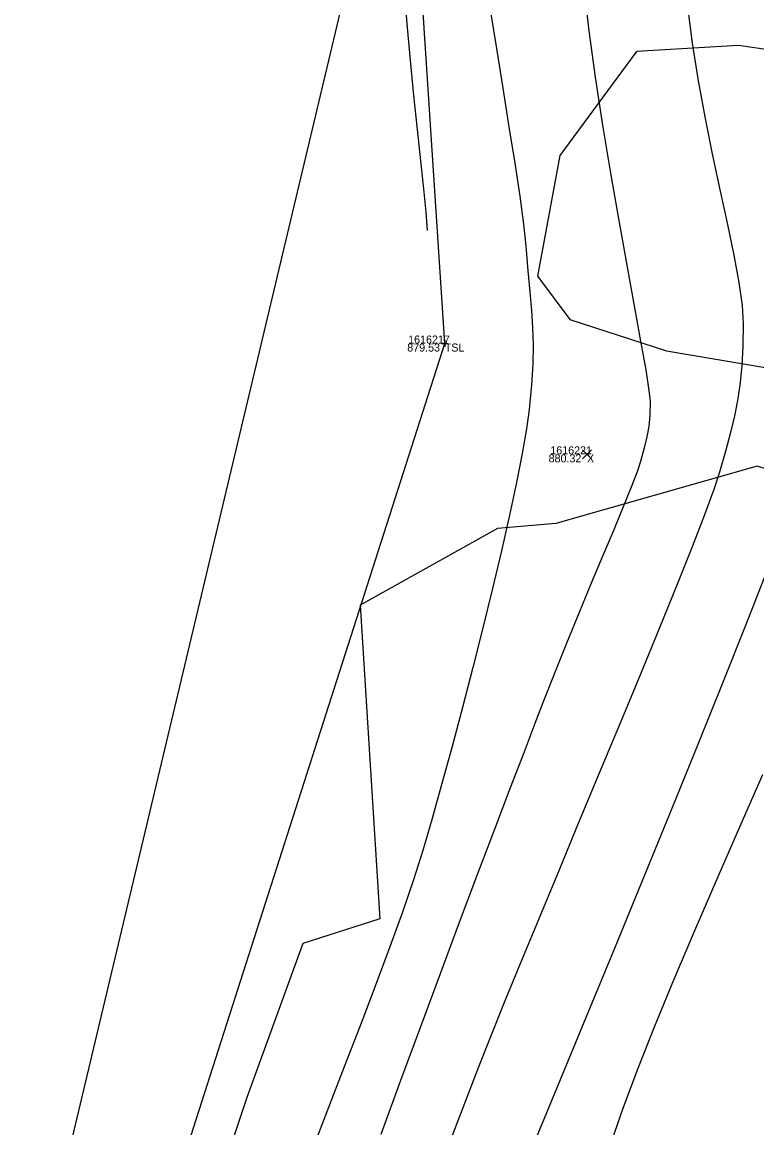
# Model space of a CAD drawing. Extents: x 1957117 to 1971063, y 701601 to 715861.
# Drawn here: x 1963273.02 to 1963305.15, y 706062.39 to 706110.73 of the extents above; entities that cross this region are included whole.
import ezdxf

# ---------------------------------------------------------------- set-up
doc = ezdxf.new("R2010")
doc.units = 0
for name, color, linetype in [('AP_X_Lights', 7, 'Continuous'), ('DT_X_Break_Line', 7, 'Continuous'), ('DT_X_Contour_Major', 7, 'Continuous'), ('DT_X_Contour_Minor', 7, 'Continuous'), ('DT_X_TIN_Hull', 7, 'Continuous'), ('HY_X_Water_Edge', 7, 'Continuous'), ('PV_P_Drive', 7, 'Continuous'), ('PV_P_Shoulder', 7, 'Continuous'), ('RS_Raster1', 7, 'Continuous'), ('SC_Scratch1', 7, 'Continuous'), ('SC_Shading5', 7, 'Continuous'), ('VG_X_Tree_Line_Rt', 7, 'Continuous')]:
    doc.layers.add(name, color=color, linetype=linetype)

msp = doc.modelspace()

# ---------------------------------------------------------------- linework, layer by layer
at = {"layer": 'AP_X_Lights'}
for p, q in [((1963297.524, 706091.639), (1963297.912, 706092.029)), ((1963297.524, 706092.029), (1963297.912, 706091.639))]:
    msp.add_line(p, q, dxfattribs=at)
at = {"layer": 'DT_X_Break_Line'}
msp.add_lwpolyline([(1963218.329, 705756.178), (1963229.265, 705808.356), (1963234.8, 705853.147), (1963240.079, 705903.468), (1963258.033, 705954.684), (1963270.287, 705999.321), (1963276.323, 706049.345), (1963291.502, 706096.678), (1963290.138, 706117.655), (1963319.921, 706191.295), (1963330.374, 706242.631), (1963344.413, 706289.409), (1963345.772, 706340.009), (1963383.117, 706434.704), (1963392.11, 706487.426), (1963408.164, 706535.687), (1963423.633, 706582.721), (1963435.242, 706630.63), (1963443.084, 706680.696), (1963464.732, 706726.815), (1963480.654, 706774.214), (1963508.465, 706799.669), (1963511.002, 706809.48)], dxfattribs=at)
at = {"layer": 'DT_X_Contour_Major'}
for points in [[(1963289.725, 706112.211), (1963289.847, 706110.647), (1963289.988, 706109.069), (1963290.14, 706107.519), (1963290.293, 706106.037), (1963290.439, 706104.666), (1963290.568, 706103.446), (1963290.671, 706102.418), (1963290.738, 706101.624)], [(1963289.725, 706112.211), (1963289.847, 706110.647), (1963289.988, 706109.069), (1963290.14, 706107.519), (1963290.293, 706106.037), (1963290.439, 706104.666), (1963290.568, 706103.446), (1963290.671, 706102.418), (1963290.738, 706101.624)], [(1963293.493, 706111.269), (1963293.759, 706109.572), (1963294.037, 706107.847), (1963294.309, 706106.155), (1963294.562, 706104.558), (1963294.779, 706103.116), (1963294.945, 706101.891), (1963295.044, 706100.942), (1963295.135, 706099.857), (1963295.219, 706098.933), (1963295.29, 706098.118), (1963295.34, 706097.358), (1963295.363, 706096.6), (1963295.352, 706095.789), (1963295.299, 706094.873), (1963295.199, 706093.797), (1963295.081, 706092.951), (1963294.892, 706091.876), (1963294.639, 706090.608), (1963294.332, 706089.178), (1963293.978, 706087.62), (1963293.587, 706085.967), (1963293.167, 706084.252), (1963292.728, 706082.509), (1963292.277, 706080.77), (1963291.824, 706079.069), (1963291.377, 706077.438), (1963290.946, 706075.911), (1963290.537, 706074.521), (1963290.13, 706073.235), (1963289.647, 706071.825), (1963289.101, 706070.31), (1963288.505, 706068.708), (1963287.87, 706067.04), (1963287.21, 706065.325), (1963286.536, 706063.582), (1963285.862, 706061.831)], [(1963293.493, 706111.269), (1963293.759, 706109.572), (1963294.037, 706107.847), (1963294.309, 706106.155), (1963294.562, 706104.558), (1963294.779, 706103.116), (1963294.945, 706101.891), (1963295.044, 706100.942), (1963295.135, 706099.857), (1963295.219, 706098.933), (1963295.29, 706098.118), (1963295.34, 706097.358), (1963295.363, 706096.6), (1963295.352, 706095.789), (1963295.299, 706094.873), (1963295.199, 706093.797), (1963295.081, 706092.951), (1963294.892, 706091.876), (1963294.639, 706090.608), (1963294.332, 706089.178), (1963293.978, 706087.62), (1963293.587, 706085.967), (1963293.167, 706084.252), (1963292.728, 706082.509), (1963292.277, 706080.77), (1963291.824, 706079.069), (1963291.377, 706077.438), (1963290.946, 706075.911), (1963290.537, 706074.521), (1963290.13, 706073.235), (1963289.647, 706071.825), (1963289.101, 706070.31), (1963288.505, 706068.708), (1963287.87, 706067.04), (1963287.21, 706065.325), (1963286.536, 706063.582), (1963285.862, 706061.831)]]:
    msp.add_lwpolyline(points, dxfattribs=at)
at = {"layer": 'DT_X_Contour_Minor'}
for points in [[(1963297.59, 706112.24), (1963297.804, 706110.352), (1963298.081, 706108.328), (1963298.402, 706106.23), (1963298.75, 706104.119), (1963299.108, 706102.058), (1963299.458, 706100.106), (1963299.783, 706098.326), (1963300.065, 706096.779), (1963300.287, 706095.527), (1963300.432, 706094.63), (1963300.482, 706094.15), (1963300.463, 706093.536), (1963300.419, 706093.045), (1963300.343, 706092.598), (1963300.227, 706092.116), (1963300.064, 706091.52), (1963299.911, 706091.064), (1963299.654, 706090.395), (1963299.309, 706089.544), (1963298.891, 706088.541), (1963298.419, 706087.415), (1963297.908, 706086.198), (1963297.375, 706084.92), (1963296.836, 706083.61), (1963296.308, 706082.299), (1963295.808, 706081.017), (1963295.441, 706080.061), (1963294.955, 706078.791), (1963294.365, 706077.248), (1963293.688, 706075.471), (1963292.939, 706073.499), (1963292.137, 706071.371), (1963291.296, 706069.129), (1963290.434, 706066.811), (1963289.567, 706064.456), (1963288.711, 706062.105)], [(1963297.59, 706112.24), (1963297.804, 706110.352), (1963298.081, 706108.328), (1963298.402, 706106.23), (1963298.75, 706104.119), (1963299.108, 706102.058), (1963299.458, 706100.106), (1963299.783, 706098.326), (1963300.065, 706096.779), (1963300.287, 706095.527), (1963300.432, 706094.63), (1963300.482, 706094.15), (1963300.463, 706093.536), (1963300.419, 706093.045), (1963300.343, 706092.598), (1963300.227, 706092.116), (1963300.064, 706091.52), (1963299.911, 706091.064), (1963299.654, 706090.395), (1963299.309, 706089.544), (1963298.891, 706088.541), (1963298.419, 706087.415), (1963297.908, 706086.198), (1963297.375, 706084.92), (1963296.836, 706083.61), (1963296.308, 706082.299), (1963295.808, 706081.017), (1963295.441, 706080.061), (1963294.955, 706078.791), (1963294.365, 706077.248), (1963293.688, 706075.471), (1963292.939, 706073.499), (1963292.137, 706071.371), (1963291.296, 706069.129), (1963290.434, 706066.811), (1963289.567, 706064.456), (1963288.711, 706062.105)], [(1963302.122, 706111.414), (1963302.319, 706109.803), (1963302.58, 706108.159), (1963302.885, 706106.513), (1963303.213, 706104.897), (1963303.545, 706103.342), (1963303.861, 706101.878), (1963304.139, 706100.537), (1963304.361, 706099.35), (1963304.505, 706098.347), (1963304.553, 706097.561), (1963304.53, 706096.566), (1963304.486, 706095.718), (1963304.415, 706094.97), (1963304.314, 706094.274), (1963304.179, 706093.582), (1963304.004, 706092.847), (1963303.785, 706092.021), (1963303.519, 706091.057), (1963303.274, 706090.304), (1963302.866, 706089.196), (1963302.318, 706087.785), (1963301.652, 706086.118), (1963300.89, 706084.246), (1963300.056, 706082.218), (1963299.172, 706080.083), (1963298.26, 706077.89), (1963297.342, 706075.689), (1963296.443, 706073.53), (1963295.583, 706071.462), (1963294.785, 706069.534), (1963294.073, 706067.795), (1963293.469, 706066.296), (1963292.994, 706065.085), (1963292.482, 706063.755), (1963291.954, 706062.395), (1963291.416, 706061.01)], [(1963302.122, 706111.414), (1963302.319, 706109.803), (1963302.58, 706108.159), (1963302.885, 706106.513), (1963303.213, 706104.897), (1963303.545, 706103.342), (1963303.861, 706101.878), (1963304.139, 706100.537), (1963304.361, 706099.35), (1963304.505, 706098.347), (1963304.553, 706097.561), (1963304.53, 706096.566), (1963304.486, 706095.718), (1963304.415, 706094.97), (1963304.314, 706094.274), (1963304.179, 706093.582), (1963304.004, 706092.847), (1963303.785, 706092.021), (1963303.519, 706091.057), (1963303.274, 706090.304), (1963302.866, 706089.196), (1963302.318, 706087.785), (1963301.652, 706086.118), (1963300.89, 706084.246), (1963300.056, 706082.218), (1963299.172, 706080.083), (1963298.26, 706077.89), (1963297.342, 706075.689), (1963296.443, 706073.53), (1963295.583, 706071.462), (1963294.785, 706069.534), (1963294.073, 706067.795), (1963293.469, 706066.296), (1963292.994, 706065.085), (1963292.482, 706063.755), (1963291.954, 706062.395), (1963291.416, 706061.01)], [(1963305.492, 706086.507), (1963304.649, 706084.355), (1963303.674, 706081.906), (1963302.591, 706079.219), (1963301.426, 706076.351), (1963300.204, 706073.361), (1963298.95, 706070.308), (1963297.689, 706067.249), (1963296.446, 706064.245), (1963295.247, 706061.352)], [(1963305.492, 706086.507), (1963304.649, 706084.355), (1963303.674, 706081.906), (1963302.591, 706079.219), (1963301.426, 706076.351), (1963300.204, 706073.361), (1963298.95, 706070.308), (1963297.689, 706067.249), (1963296.446, 706064.245), (1963295.247, 706061.352)], [(1963305.389, 706077.823), (1963304.39, 706075.542), (1963303.394, 706073.257), (1963302.424, 706071.009), (1963301.503, 706068.841), (1963300.657, 706066.794), (1963299.908, 706064.911), (1963299.281, 706063.234), (1963298.799, 706061.804)], [(1963305.389, 706077.823), (1963304.39, 706075.542), (1963303.394, 706073.257), (1963302.424, 706071.009), (1963301.503, 706068.841), (1963300.657, 706066.794), (1963299.908, 706064.911), (1963299.281, 706063.234), (1963298.799, 706061.804)]]:
    msp.add_lwpolyline(points, dxfattribs=at)
at = {"layer": 'DT_X_TIN_Hull'}
msp.add_lwpolyline([(1963495.509, 706817.37), (1963480.654, 706774.214), (1963464.732, 706726.815), (1963443.084, 706680.696), (1963439.989, 706681.954), (1963422.341, 706634.767), (1963409.759, 706587.541), (1963383.299, 706489.662), (1963371.06, 706438.048), (1963369.543, 706438.68), (1963344.28, 706340.158), (1963318.949, 706243.571), (1963307.297, 706195.415), (1963288.342, 706117.136), (1963272.445, 706050.395), (1963261.075, 706002.095), (1963254.734, 705951.873), (1963238.207, 705904.757)], dxfattribs=at)
at = {"layer": 'HY_X_Water_Edge'}
msp.add_spline([(1963191.723, 701994.048), (1963062.047, 702441.167), (1962863.491, 703169.356), (1962827.53, 703438.691), (1962823.213, 703537.412), (1962817.962, 703593.874), (1962817.97, 703697.316), (1962828.582, 703804.235), (1962836.461, 703844.734), (1962850.687, 703896.004), (1962867.251, 703938.846), (1962873.848, 703992.355), (1962884.135, 704091.371), (1962891.241, 704140.854), (1962897.382, 704180.529), (1962905.467, 704230.979), (1962943.949, 704328.022), (1962948.537, 704378.842), (1962964.114, 704426.264), (1963004.885, 704570.73), (1963042.054, 704716.522), (1963062.038, 704814.417), (1963072.171, 704860.237), (1963090.023, 704956.798), (1963107.066, 705031.783), (1963133.773, 705105.742), (1963148.685, 705206.74), (1963175.48, 705301.059), (1963191.635, 705353.417), (1963210.988, 705447.286), (1963219.532, 705497.27), (1963230.124, 705549.475), (1963251.052, 705591.159), (1963275.289, 705693.429), (1963292.982, 705784.032), (1963302.841, 705839.645), (1963335.126, 705936.766), (1963359.752, 706046.75), (1963389.133, 706177.299), (1963417.827, 706273.456), (1963475.868, 706451.902), (1963533.782, 706640.53), (1963553.86, 706696.984), (1963580.184, 706715.425), (1963609.172, 706718.73), (1963617.062, 706714.691), (1963619.447, 706694.678), (1963564.282, 706533.07), (1963531.853, 706395.229), (1963434.4, 706006.96), (1963354.09, 705679.186), (1963237.513, 705206.07), (1963167.369, 704892.962), (1963059.145, 704434.176), (1962907.914, 703908.742), (1962877.458, 703703.326), (1962898.357, 703412.121), (1962942.65, 703052.267), (1963048.963, 702674.866), (1963191.468, 702189.666), (1963245.396, 702019.832)], degree=3, dxfattribs=at)
at = {"layer": 'PV_P_Drive'}
for p, q in [((1963291.356, 706096.678), (1963291.648, 706096.678)), ((1963291.502, 706096.824), (1963291.502, 706096.532)), ((1963291.502, 706096.678), (1963291.502, 706096.678))]:
    msp.add_line(p, q, dxfattribs=at)
at = {"layer": 'SC_Shading5'}
for points in [[(1963026.912, 704294.121), (1963138.818, 704737.794), (1963251.679, 705213.963), (1963374.306, 705730.111), (1963454.783, 706045.593), (1963517.244, 706296.713), (1963562.763, 706479.256), (1963580.13, 706553.799), (1963589.678, 706586.994)], [(1963609.915, 706579.703), (1963587.283, 706499.153), (1963552.056, 706354.005), (1963480.911, 706069.234), (1963357.401, 705576.869), (1963272.751, 705226.931), (1963210.247, 704956.481), (1963044.97, 704288.881)]]:
    msp.add_spline(points, degree=3, dxfattribs=at)
at = {"layer": 'VG_X_Tree_Line_Rt'}
msp.add_lwpolyline([(1963319.336, 706112.573), (1963312.053, 706108.824), (1963310.725, 706108.769), (1963304.339, 706109.705), (1963299.885, 706109.439), (1963296.528, 706104.896), (1963295.557, 706099.62), (1963296.969, 706097.729), (1963301.197, 706096.361), (1963306.806, 706095.408), (1963311.711, 706092.74), (1963311.059, 706089.437), (1963305.167, 706091.31), (1963296.365, 706088.812), (1963293.809, 706088.593), (1963287.798, 706085.237), (1963288.243, 706078.256), (1963288.656, 706071.535), (1963285.294, 706070.456), (1963282.846, 706063.715), (1963281.227, 706058.865)], dxfattribs=at)

# ---------------------------------------------------------------- texts
at = {"layer": 'PV_P_Shoulder'}
for s, p in [('879.53', (1963289.862, 706096.328)), ('880.32', (1963296.043, 706091.484))]:
    msp.add_text(s, height=0.35, dxfattribs=at).set_placement(p)
at = {"layer": 'RS_Raster1'}
for s, p in [('1616217', (1963289.901, 706096.678)), ('1616221', (1963296.117, 706091.834))]:
    msp.add_text(s, height=0.35, dxfattribs=at).set_placement(p)
at = {"layer": 'SC_Scratch1'}
for s, p in [('TSL', (1963291.502, 706096.328)), ('X', (1963297.718, 706091.484))]:
    msp.add_text(s, height=0.35, dxfattribs=at).set_placement(p)

doc.saveas('drawing.dxf')
